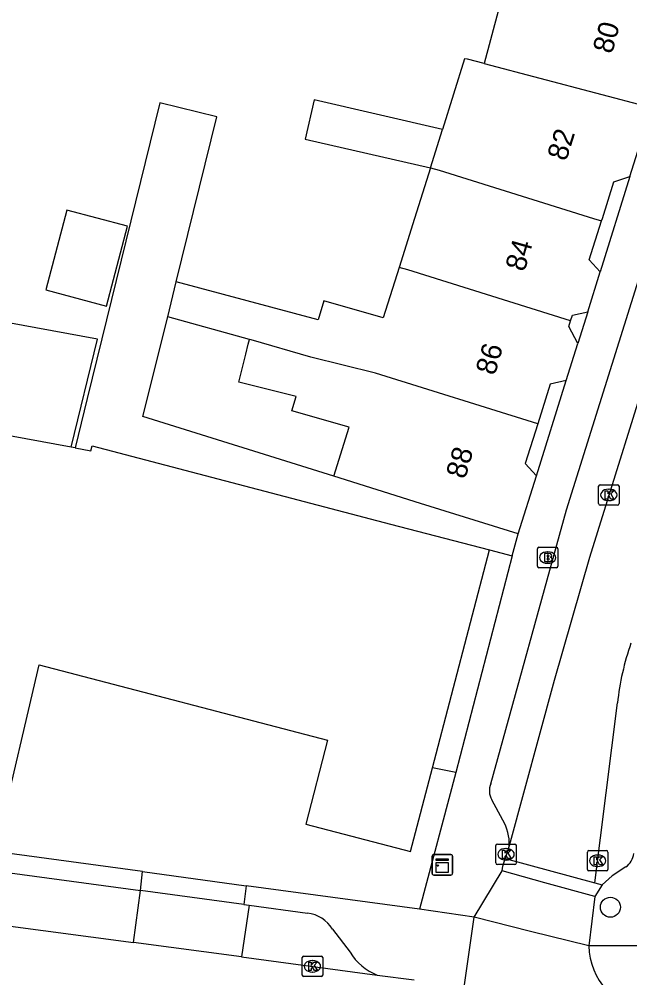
# Model space of a CAD drawing. Extents: x 161845 to 162341, y 381620 to 382158.
# Drawn here: x 161892.92 to 161922.78, y 381712.86 to 381759.75 of the extents above; entities that cross this region are included whole.
import ezdxf

# ---------------------------------------------------------------- set-up
doc = ezdxf.new("R2010")
doc.units = 0
for name, color, linetype in [('IMGEO_Boom', 7, 'Continuous'), ('IMGEO_Brandkraan', 7, 'Continuous'), ('IMGEO_Hek', 7, 'Continuous'), ('IMGEO_Kast', 7, 'Continuous'), ('IMGEO_Kolk', 7, 'Continuous'), ('IMGEO_Pand', 7, 'Continuous'), ('IMGEO_Pand_nummerreeks', 7, 'Continuous'), ('IMGEO_Rijbaan_lokaal_open', 7, 'Continuous'), ('IMGEO_Voetpad_open', 7, 'Continuous')]:
    doc.layers.add(name, color=color, linetype=linetype)

msp = doc.modelspace()

# ---------------------------------------------------------------- linework, layer by layer
at = {"layer": 'IMGEO_Boom'}
msp.add_circle((161921.832, 381716.311), 0.489, dxfattribs=at)
at = {"layer": 'IMGEO_Brandkraan'}
for p, q in [((161918.266, 381732.989), (161918.266, 381733.841)), ((161918.341, 381733.915), (161919.193, 381733.915)), ((161918.754, 381733.695), (161918.779, 381733.695)), ((161919.267, 381733.841), (161919.267, 381732.989)), ((161919.193, 381732.915), (161918.341, 381732.915)), ((161918.777, 381733.135), (161918.752, 381733.135))]:
    msp.add_line(p, q, dxfattribs=at)
for points in [[(161918.266, 381732.989), (161918.266, 381733.841)], [(161918.341, 381733.915), (161919.193, 381733.915)], [(161919.267, 381733.841), (161919.267, 381732.989)], [(161918.614, 381733.615), (161918.614, 381733.215), (161918.827, 381733.215)], [(161918.845, 381733.615), (161918.614, 381733.615)], [(161918.793, 381733.534), (161918.739, 381733.534), (161918.739, 381733.458)], [(161918.739, 381733.458), (161918.792, 381733.458)], [(161918.801, 381733.382), (161918.739, 381733.382), (161918.739, 381733.301)], [(161918.739, 381733.301), (161918.801, 381733.301)], [(161919.193, 381732.915), (161918.341, 381732.915)]]:
    msp.add_lwpolyline(points, dxfattribs=at)
for centre, radius, start, end in [((161918.343, 381733.839), 0.0765, 91.552, 178.448), ((161918.343, 381733.839), 0.0765, 91.552, 178.448), ((161919.191, 381733.839), 0.0765, 1.552, 88.448), ((161919.191, 381733.839), 0.0765, 1.552, 88.448), ((161918.794, 381733.496), 0.0379, 267.8285, 90.9355), ((161918.802, 381733.341), 0.0404, 269.8759, 90.5077), ((161918.833, 381733.466), 0.251, 268.6676, 293.5347), ((161918.849, 381733.47), 0.145, 59.4692, 91.5367), ((161918.874, 381733.517), 0.0922, 285.5137, 58.1501), ((161918.879, 381733.325), 0.105, 301.3115, 78.989), ((161918.343, 381732.991), 0.0765, 181.552, 268.448), ((161918.343, 381732.991), 0.0765, 181.552, 268.448), ((161919.191, 381732.991), 0.0765, 271.552, 358.448), ((161919.191, 381732.991), 0.0765, 271.552, 358.448)]:
    msp.add_arc(centre, radius, start, end, dxfattribs=at)
for centre, major_axis, ratio, start_param, end_param in [((161918.753, 381733.415), (-0.387, 0.002), 0.722429, 4.712389, 7.853982), ((161918.778, 381733.415), (-0.39, 0.002), 0.717154, 1.570796, 4.712389)]:
    msp.add_ellipse(centre, major_axis=major_axis, ratio=ratio, start_param=start_param, end_param=end_param, dxfattribs=at)
at = {"layer": 'IMGEO_Hek'}
msp.add_lwpolyline([(161917.032, 381733.501), (161914.271, 381722.897)], dxfattribs=at)
at = {"layer": 'IMGEO_Kast'}
for p, q in [((161913.112, 381717.96), (161913.112, 381718.801)), ((161913.112, 381718.801), (161913.112, 381717.96)), ((161913.187, 381718.885), (161914.028, 381718.885)), ((161914.028, 381718.885), (161913.187, 381718.885)), ((161914.112, 381718.81), (161914.112, 381717.969)), ((161914.112, 381717.969), (161914.112, 381718.81)), ((161914.037, 381717.885), (161913.196, 381717.885)), ((161913.196, 381717.885), (161914.037, 381717.885))]:
    msp.add_line(p, q, dxfattribs=at)
for points in [[(161913.307, 381718.675), (161913.907, 381718.675), (161913.907, 381718.59), (161913.307, 381718.59), (161913.307, 381718.675)], [(161913.307, 381718.5), (161913.907, 381718.5), (161913.907, 381718.011), (161913.307, 381718.011), (161913.307, 381718.5)]]:
    msp.add_lwpolyline(points, dxfattribs=at)
msp.add_circle((161913.391, 381718.349), 0.0377, dxfattribs=at)
for centre, start, end in [((161913.19, 381718.807), 92.4484, 184.2845), ((161913.19, 381718.807), 92.4484, 184.2845), ((161914.034, 381718.807), 2.4484, 94.2845), ((161914.034, 381718.807), 2.4484, 94.2845), ((161913.19, 381717.963), 182.4484, 274.2845), ((161913.19, 381717.963), 182.4484, 274.2845), ((161914.034, 381717.963), 272.4484, 4.2845), ((161914.034, 381717.963), 272.4484, 4.2845)]:
    msp.add_arc(centre, 0.0779, start, end, dxfattribs=at)
at = {"layer": 'IMGEO_Kolk'}
for p, q in [((161921.331, 381736.979), (161922.183, 381736.979)), ((161921.256, 381736.053), (161921.256, 381736.905)), ((161921.744, 381736.759), (161921.769, 381736.759)), ((161922.257, 381736.905), (161922.257, 381736.053)), ((161921.767, 381736.199), (161921.742, 381736.199)), ((161922.183, 381735.979), (161921.331, 381735.979)), ((161916.232, 381718.474), (161916.232, 381719.326)), ((161916.307, 381719.4), (161917.159, 381719.4)), ((161916.72, 381719.18), (161916.745, 381719.18)), ((161917.233, 381719.326), (161917.233, 381718.474)), ((161920.711, 381718.157), (161920.711, 381719.009)), ((161920.786, 381719.083), (161921.638, 381719.083)), ((161921.199, 381718.863), (161921.224, 381718.863)), ((161921.712, 381719.009), (161921.712, 381718.157)), ((161917.159, 381718.4), (161916.307, 381718.4)), ((161916.743, 381718.62), (161916.718, 381718.62)), ((161921.222, 381718.303), (161921.197, 381718.303)), ((161921.638, 381718.083), (161920.786, 381718.083)), ((161906.762, 381712.992), (161906.762, 381713.844)), ((161906.837, 381713.918), (161907.689, 381713.918)), ((161907.25, 381713.698), (161907.275, 381713.698)), ((161907.763, 381713.844), (161907.763, 381712.992)), ((161907.273, 381713.138), (161907.248, 381713.138)), ((161907.689, 381712.918), (161906.837, 381712.918))]:
    msp.add_line(p, q, dxfattribs=at)
for points in [[(161921.331, 381736.979), (161922.183, 381736.979)], [(161921.256, 381736.053), (161921.256, 381736.905)], [(161921.577, 381736.679), (161921.7, 381736.679), (161921.7, 381736.528), (161921.83, 381736.679), (161921.994, 381736.679), (161921.848, 381736.528), (161922.001, 381736.279), (161921.849, 381736.279), (161921.764, 381736.443), (161921.7, 381736.376), (161921.7, 381736.279), (161921.577, 381736.279), (161921.577, 381736.679)], [(161922.257, 381736.905), (161922.257, 381736.053)], [(161922.183, 381735.979), (161921.331, 381735.979)], [(161916.232, 381718.474), (161916.232, 381719.326)], [(161916.307, 381719.4), (161917.159, 381719.4)], [(161917.233, 381719.326), (161917.233, 381718.474)], [(161916.553, 381719.1), (161916.676, 381719.1), (161916.676, 381718.949), (161916.806, 381719.1), (161916.97, 381719.1), (161916.824, 381718.949), (161916.977, 381718.7), (161916.825, 381718.7), (161916.74, 381718.864), (161916.676, 381718.797), (161916.676, 381718.7), (161916.553, 381718.7), (161916.553, 381719.1)], [(161920.711, 381718.157), (161920.711, 381719.009)], [(161920.786, 381719.083), (161921.638, 381719.083)], [(161921.032, 381718.783), (161921.155, 381718.783), (161921.155, 381718.632), (161921.285, 381718.783), (161921.449, 381718.783), (161921.303, 381718.632), (161921.456, 381718.383), (161921.304, 381718.383), (161921.219, 381718.547), (161921.155, 381718.48), (161921.155, 381718.383), (161921.032, 381718.383), (161921.032, 381718.783)], [(161921.712, 381719.009), (161921.712, 381718.157)], [(161917.159, 381718.4), (161916.307, 381718.4)], [(161921.638, 381718.083), (161920.786, 381718.083)], [(161906.762, 381712.992), (161906.762, 381713.844)], [(161906.837, 381713.918), (161907.689, 381713.918)], [(161907.083, 381713.618), (161907.206, 381713.618), (161907.206, 381713.467), (161907.336, 381713.618), (161907.5, 381713.618), (161907.354, 381713.467), (161907.507, 381713.218), (161907.355, 381713.218), (161907.27, 381713.382), (161907.206, 381713.315), (161907.206, 381713.218), (161907.083, 381713.218), (161907.083, 381713.618)], [(161907.763, 381713.844), (161907.763, 381712.992)], [(161907.689, 381712.918), (161906.837, 381712.918)]]:
    msp.add_lwpolyline(points, dxfattribs=at)
for centre, start, end in [((161921.333, 381736.903), 91.552, 178.448), ((161921.333, 381736.903), 91.552, 178.448), ((161922.181, 381736.903), 1.552, 88.448), ((161922.181, 381736.903), 1.552, 88.448), ((161921.333, 381736.055), 181.552, 268.448), ((161921.333, 381736.055), 181.552, 268.448), ((161922.181, 381736.055), 271.552, 358.448), ((161922.181, 381736.055), 271.552, 358.448), ((161916.309, 381719.324), 91.552, 178.448), ((161916.309, 381719.324), 91.552, 178.448), ((161917.157, 381719.324), 1.552, 88.448), ((161917.157, 381719.324), 1.552, 88.448), ((161920.788, 381719.007), 91.552, 178.448), ((161920.788, 381719.007), 91.552, 178.448), ((161921.636, 381719.007), 1.552, 88.448), ((161921.636, 381719.007), 1.552, 88.448), ((161916.309, 381718.476), 181.552, 268.448), ((161916.309, 381718.476), 181.552, 268.448), ((161917.157, 381718.476), 271.552, 358.448), ((161917.157, 381718.476), 271.552, 358.448), ((161920.788, 381718.159), 181.552, 268.448), ((161920.788, 381718.159), 181.552, 268.448), ((161921.636, 381718.159), 271.552, 358.448), ((161921.636, 381718.159), 271.552, 358.448), ((161906.839, 381713.842), 91.552, 178.448), ((161906.839, 381713.842), 91.552, 178.448), ((161907.687, 381713.842), 1.552, 88.448), ((161907.687, 381713.842), 1.552, 88.448), ((161906.839, 381712.994), 181.552, 268.448), ((161906.839, 381712.994), 181.552, 268.448), ((161907.687, 381712.994), 271.552, 358.448), ((161907.687, 381712.994), 271.552, 358.448)]:
    msp.add_arc(centre, 0.0765, start, end, dxfattribs=at)
for centre, major_axis, ratio, start_param, end_param in [((161921.743, 381736.479), (-0.387, 0.002), 0.722429, 4.712389, 7.853982), ((161921.768, 381736.479), (-0.39, 0.002), 0.717154, 1.570796, 4.712389), ((161916.719, 381718.9), (-0.387, 0.002), 0.722429, 4.712389, 7.853982), ((161916.744, 381718.9), (-0.39, 0.002), 0.717154, 1.570796, 4.712389), ((161921.198, 381718.583), (-0.387, 0.002), 0.722429, 4.712389, 7.853982), ((161921.223, 381718.583), (-0.39, 0.002), 0.717154, 1.570796, 4.712389), ((161907.249, 381713.418), (-0.387, 0.002), 0.722429, 4.712389, 7.853982), ((161907.274, 381713.418), (-0.39, 0.002), 0.717154, 1.570796, 4.712389)]:
    msp.add_ellipse(centre, major_axis=major_axis, ratio=ratio, start_param=start_param, end_param=end_param, dxfattribs=at)
at = {"layer": 'IMGEO_Pand'}
for points in [[(161917.1, 381762.969), (161915.662, 381757.574)], [(161915.662, 381757.574), (161914.848, 381757.787), (161914.701, 381757.815), (161913.619, 381754.359)], [(161915.662, 381757.574), (161923.832, 381755.432)], [(161913.619, 381754.359), (161907.345, 381755.798), (161906.907, 381753.886), (161913.031, 381752.482)], [(161922.777, 381752.053), (161923.772, 381755.207), (161923.832, 381755.432)], [(161913.031, 381752.482), (161913.619, 381754.359)], [(161913.031, 381752.482), (161912.253, 381750), (161911.501, 381747.601)], [(161913.031, 381752.482), (161913.46, 381752.366), (161921.01, 381750), (161921.4, 381749.878)], [(161921.4, 381749.878), (161921.439, 381750), (161922.002, 381751.786), (161922.777, 381752.053)], [(161894.223, 381746.504), (161897.185, 381745.719), (161898.219, 381749.622), (161895.256, 381750.407), (161894.223, 381746.504)], [(161921.338, 381747.387), (161920.799, 381747.972), (161921.4, 381749.878)], [(161911.501, 381747.601), (161910.729, 381745.136), (161907.818, 381745.978), (161907.547, 381745.04), (161900.603, 381746.898)], [(161919.889, 381744.99), (161911.931, 381747.484), (161911.501, 381747.601)], [(161920.725, 381745.432), (161921.338, 381747.387)], [(161900.186, 381745.198), (161900.603, 381746.898)], [(161895.471, 381738.811), (161896.758, 381744.105), (161888.673, 381745.589), (161888.7, 381745.739), (161888.742, 381745.964), (161888.762, 381746.077), (161888.814, 381746.358)], [(161919.889, 381744.99), (161919.975, 381745.264), (161920.725, 381745.432)], [(161904.185, 381744.088), (161900.186, 381745.198)], [(161920.239, 381743.88), (161919.803, 381744.714), (161919.889, 381744.99)], [(161908.304, 381737.397), (161909.054, 381739.79), (161906.262, 381740.597), (161906.465, 381741.301), (161903.668, 381741.987), (161904.005, 381743.36), (161904.127, 381743.854), (161904.185, 381744.088)], [(161918.278, 381739.958), (161910.351, 381742.442), (161907.187, 381743.221), (161904.269, 381744.065), (161904.185, 381744.088)], [(161919.673, 381742.076), (161920.239, 381743.88)], [(161895.471, 381738.811), (161882.761, 381741.144), (161875.98, 381742.352)], [(161919.673, 381742.076), (161918.886, 381741.9), (161918.278, 381739.958)], [(161918.278, 381739.958), (161917.669, 381738.015), (161918.217, 381737.419)], [(161895.655, 381738.777), (161896.431, 381738.635), (161896.494, 381738.873), (161911.085, 381735.053), (161915.922, 381733.787)], [(161895.655, 381738.777), (161895.471, 381738.811)], [(161917.325, 381734.571), (161918.217, 381737.419)], [(161917.325, 381734.571), (161912.554, 381736.066), (161908.304, 381737.397)], [(161913.133, 381723.134), (161915.922, 381733.787)], [(161887.622, 381719.595), (161887.784, 381720.479), (161891.913, 381719.721), (161893.893, 381728.171), (161908.006, 381724.477), (161906.933, 381720.378), (161912.06, 381719.035), (161913.133, 381723.134)]]:
    msp.add_lwpolyline(points, dxfattribs=at)
at = {"layer": 'IMGEO_Rijbaan_lokaal_open'}
for points in [[(161928.855, 381760.062), (161927.557, 381755.075), (161920.816, 381733.424), (161919.084, 381727.401), (161916.883, 381719.321)], [(161921.068, 381717.499), (161922.182, 381726.301)], [(161916.883, 381719.321), (161916.695, 381718.702)], [(161916.695, 381718.702), (161921.068, 381717.499)], [(161869.911, 381718.389), (161898.507, 381714.581)], [(161915.172, 381715.818), (161916.534, 381718.098)], [(161921.065, 381716.828), (161918.63, 381717.51), (161916.534, 381718.098)], [(161921.065, 381716.828), (161920.785, 381714.418)], [(161914.683, 381712.406), (161915.172, 381715.818)], [(161920.785, 381714.418), (161917.929, 381715.13), (161915.172, 381715.818)], [(161903.797, 381713.876), (161898.507, 381714.581)], [(161903.797, 381713.876), (161910.432, 381712.993)], [(161910.432, 381712.993), (161912.231, 381712.753)]]:
    msp.add_lwpolyline(points, dxfattribs=at)
for centre, radius, start, end in [((161934.786, 381724.996), 12.672, 160.5333, 174.0891), ((161923.964, 381714.443), 3.179, 180.4515, 265.3958)]:
    msp.add_arc(centre, radius, start, end, dxfattribs=at)
at = {"layer": 'IMGEO_Voetpad_open'}
for points in [[(161915.985, 381722.354), (161919.692, 381735.743), (161924.159, 381750), (161925.028, 381752.783), (161925.871, 381755.689), (161928.167, 381764.412), (161929.028, 381768.381), (161930.019, 381773.8)], [(161900.603, 381746.898), (161902.585, 381754.979), (161899.797, 381755.663), (161896.247, 381741.19), (161895.655, 381738.777)], [(161922.777, 381752.053), (161921.338, 381747.387)], [(161920.725, 381745.432), (161920.239, 381743.88)], [(161908.304, 381737.397), (161898.976, 381740.318), (161900.186, 381745.198)], [(161918.217, 381737.419), (161919.673, 381742.076)], [(161917.032, 381733.501), (161917.325, 381734.571)], [(161915.922, 381733.787), (161917.032, 381733.501)], [(161917.032, 381733.501), (161914.271, 381722.897)], [(161914.271, 381722.897), (161912.504, 381716.211)], [(161914.271, 381722.897), (161913.133, 381723.134)], [(161916.572, 381720.573), (161916.037, 381721.571)], [(161873.478, 381720.533), (161875.325, 381720.308), (161898.861, 381717.122)], [(161898.959, 381718.053), (161887.622, 381719.595)], [(161916.534, 381718.098), (161916.581, 381718.326), (161916.695, 381718.702)], [(161922.585, 381718.282), (161921.913, 381717.842), (161921.433, 381717.398)], [(161898.861, 381717.122), (161898.959, 381718.053)], [(161898.959, 381718.053), (161904.028, 381717.364)], [(161904.028, 381717.364), (161903.906, 381716.439)], [(161912.504, 381716.211), (161904.028, 381717.364)], [(161921.433, 381717.398), (161921.065, 381716.828)], [(161921.068, 381717.499), (161921.433, 381717.398)], [(161898.507, 381714.581), (161898.861, 381717.122)], [(161903.906, 381716.439), (161898.861, 381717.122)], [(161904.162, 381716.404), (161903.797, 381713.876)], [(161903.906, 381716.439), (161904.162, 381716.404)], [(161904.162, 381716.404), (161907.02, 381716.017)], [(161915.172, 381715.818), (161912.504, 381716.211)], [(161908.244, 381715.237), (161909.101, 381714.113)], [(161923.835, 381714.426), (161920.785, 381714.418)]]:
    msp.add_lwpolyline(points, dxfattribs=at)
for centre, radius, start, end in [((161916.761, 381722.012), 0.848, 156.2418, 211.3572), ((161914.656, 381719.432), 2.23, 357.1383, 30.7618), ((161922.057, 381719.039), 0.923, 304.9129, 353.5986), ((161906.85, 381714.4), 1.626, 30.9925, 83.9924), ((161911.381, 381715.472), 2.654, 210.7932, 249.0474)]:
    msp.add_arc(centre, radius, start, end, dxfattribs=at)

# ---------------------------------------------------------------- texts
at = {"layer": 'IMGEO_Pand_nummerreeks'}
for s, rotation, p in [('80', 74.983, (161921.915, 381758.018)), ('82', 72.4963, (161919.668, 381752.766)), ('84', 74.0341, (161917.634, 381747.362)), ('86', 74.0319, (161916.182, 381742.289)), ('88', 74.0319, (161914.731, 381737.219))]:
    msp.add_text(s, height=1, rotation=rotation, dxfattribs=at).set_placement(p)

doc.saveas('drawing.dxf')
